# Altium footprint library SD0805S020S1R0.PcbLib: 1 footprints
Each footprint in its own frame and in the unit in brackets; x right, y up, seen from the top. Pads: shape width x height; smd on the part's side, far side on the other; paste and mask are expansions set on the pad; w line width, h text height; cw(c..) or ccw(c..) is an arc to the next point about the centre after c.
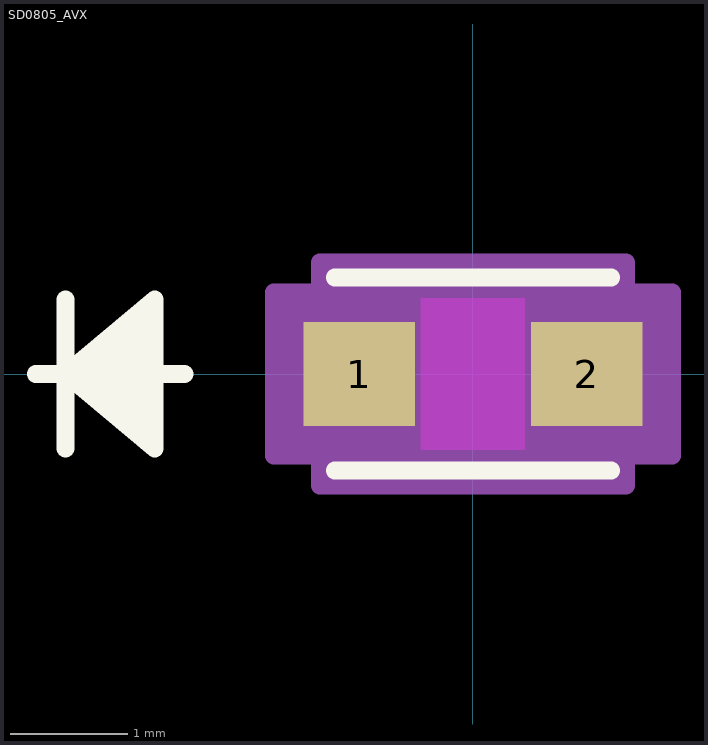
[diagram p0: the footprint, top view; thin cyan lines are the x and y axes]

## SD0805_AVX [mil]
pads (2):
  rect 37.5x35 smd paste+0 mask+0: 1(-38.25,0) 2(38.25,0)
Top Layer keep-out:
  region: -17.5,-25.5 -17.5,25.5 17.5,25.5 17.5,-25.5
Top Overlay:
  lines w6: -147,0 -97,0 ; -137,-25 -137,25 ; -107,-20 -137,0 ; -107,-15 -137,0 ; -107,-10 -137,0 ; -107,-5 -137,0 ; -107,5 -137,0 ; -107,10 -137,0 ; -107,15 -137,0 ; -107,20 -137,0 ; -46.5,-32.5 46.5,-32.5 ; -46.5,32.5 46.5,32.5 ; -137,0 -107,25 -107,-25 -137,0
Mechanical 13:
  lines w1: -147,0 -97,0 ; -137,-25 -137,25 ; -107,-20 -137,0 ; -107,-15 -137,0 ; -107,-10 -137,0 ; -107,-5 -137,0 ; -107,5 -137,0 ; -107,10 -137,0 ; -107,15 -137,0 ; -107,20 -137,0 ; -137,0 -107,25 -107,-25 -137,0 ; -41.5,-27.5 41.5,-27.5 41.5,27.5 -41.5,27.5 -41.5,-27.5
Mechanical 15:
  region: -51.5,-27.5 -67,-27.5 -67,27.5 -51.5,27.5 -51.5,37.5 51.5,37.5 51.5,27.5 67,27.5 67,-27.5 51.5,-27.5 51.5,-37.5 -51.5,-37.5
  lines w6: -67,-27.5 -67,27.5 -51.5,27.5 -51.5,37.5 51.5,37.5 51.5,27.5 67,27.5 67,-27.5 51.5,-27.5 51.5,-37.5 -51.5,-37.5 -51.5,-27.5 -67,-27.5
3D body "SD0805_AVX.step": height 39.02, standoff 0, extent -41.5,-27.6 41.5,27.6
